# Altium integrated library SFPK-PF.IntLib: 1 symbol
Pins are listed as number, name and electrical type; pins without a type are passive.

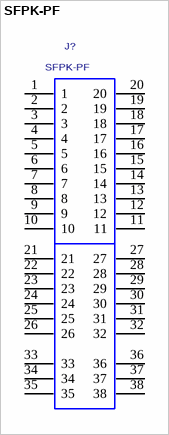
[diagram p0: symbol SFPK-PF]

## SFPK-PF
designator J?
SOLDER LEADS COMBO.; MANUFACTURER: SAMTEC
footprint SFPK-PF
pins: 1, 2, 3, 4, 5, 6, 7, 8, 9, 10, 11, 12, 13, 14, 15, 16, 17, 18, 19, 20, 21, 22, 23, 24, 25, 26, 27, 28, 29, 30, 31, 32, 33, 34, 35, 36, 37, 38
